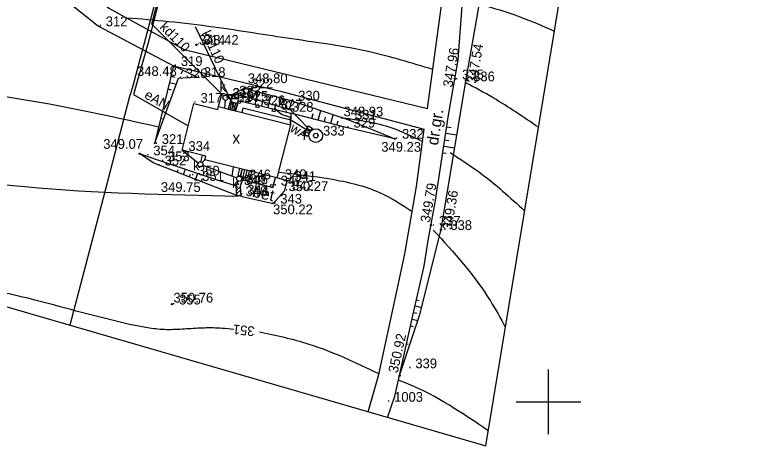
# Model space of a CAD drawing. Extents: x 4632591 to 4653165, y 5351032 to 5369868.
# Drawn here: x 4644617.6 to 4644733.1, y 5358293.2 to 5358359.7 of the extents above; entities that cross this region are included whole.
import ezdxf

# ---------------------------------------------------------------- set-up
doc = ezdxf.new("R2010")
doc.units = 0
for name, color, linetype in [('EBTPO_346', 7, 'Continuous'), ('EBTPO_352', 7, 'Continuous'), ('EBUPO_314', 7, 'Continuous'), ('EBUPP_312', 7, 'Continuous'), ('EBUPP_316', 7, 'Continuous'), ('EUZPU_424', 7, 'Continuous'), ('SDRPK_423', 7, 'Continuous'), ('UEEPO_585', 7, 'Continuous'), ('UKKPA_506', 7, 'Continuous'), ('UKKPA_509', 7, 'Continuous'), ('UKKPB_562', 7, 'Continuous'), ('UWWPA_907', 7, 'Continuous'), ('UWWPO_581', 7, 'Continuous'), ('Warstwa 40', 7, 'Continuous'), ('Warstwa 60', 7, 'Continuous'), ('Warstwa 62', 7, 'Continuous'), ('WUKPS_403', 7, 'Continuous'), ('WUKPS_820', 7, 'Continuous'), ('WUKPS_823', 7, 'Continuous'), ('WUKPS_824', 7, 'Continuous'), ('WWRPH_811', 7, 'Continuous')]:
    doc.layers.add(name, color=color, linetype=linetype)

msp = doc.modelspace()

# ---------------------------------------------------------------- linework, layer by layer
at = {"layer": 'EBTPO_346'}
for points in [[(4644652.02, 5358346.12), (4644652.11, 5358346.5), (4644652.51, 5358346.4), (4644652.42, 5358346.02)], [(4644654.81, 5358345.46), (4644654.91, 5358345.84), (4644655.31, 5358345.74), (4644655.21, 5358345.36)], [(4644657.33, 5358344.85), (4644657.43, 5358345.23), (4644657.83, 5358345.13), (4644657.73, 5358344.75)], [(4644652.78, 5358334.26), (4644652.88, 5358334.64), (4644653.28, 5358334.54), (4644653.19, 5358334.16)], [(4644657.05, 5358333.18), (4644657.14, 5358333.56), (4644657.54, 5358333.46), (4644657.45, 5358333.08)]]:
    msp.add_lwpolyline(points, close=True, dxfattribs=at)
at = {"layer": 'EBTPO_352'}
for p, q in [((4644650.85, 5358346.31), (4644650.56, 5358345.18)), ((4644650.84, 5358345.11), (4644651.12, 5358346.24)), ((4644651.13, 5358345.03), (4644651.42, 5358346.16)), ((4644651.42, 5358344.96), (4644651.71, 5358346.09)), ((4644651.99, 5358346.02), (4644651.7, 5358344.89)), ((4644652.71, 5358335.89), (4644652.45, 5358334.86)), ((4644652.45, 5358334.86), (4644652.71, 5358335.89)), ((4644653.09, 5358335.8), (4644652.82, 5358334.76)), ((4644653.45, 5358335.7), (4644653.18, 5358334.67)), ((4644653.8, 5358335.61), (4644653.54, 5358334.58))]:
    msp.add_line(p, q, dxfattribs=at)
for points in [[(4644651.99, 5358346.02), (4644650.85, 5358346.31), (4644650.56, 5358345.18), (4644651.7, 5358344.89)], [(4644652.32, 5358335.99), (4644652.06, 5358334.95), (4644653.93, 5358334.48), (4644654.19, 5358335.52)]]:
    msp.add_lwpolyline(points, close=True, dxfattribs=at)
at = {"layer": 'EBUPO_314'}
msp.add_line((4644652.02, 5358346.12), (4644651.7, 5358344.89), dxfattribs=at)
for points in [[(4644652.51, 5358346.4), (4644654.91, 5358345.84), (4644655.31, 5358345.74), (4644657.43, 5358345.23), (4644657.83, 5358345.13), (4644660.21, 5358344.54), (4644660.15, 5358342.76)], [(4644652.9, 5358334.74), (4644652.78, 5358334.26), (4644653.19, 5358334.16), (4644657.45, 5358333.08), (4644657.83, 5358334.6)]]:
    msp.add_lwpolyline(points, dxfattribs=at)
at = {"layer": 'EBUPP_312'}
msp.add_lwpolyline([(4644649.07, 5358345.55), (4644660.15, 5358342.76), (4644658.07, 5358334.54), (4644646.96, 5358337.34), (4644647.1, 5358337.91), (4644643.44, 5358338.83), (4644645.25, 5358346.01), (4644648.95, 5358345.08), (4644649.07, 5358345.55)], dxfattribs=at)
at = {"layer": 'EBUPP_316'}
for p, q in [((4644651.85, 5358332.63), (4644652.41, 5358333.11)), ((4644651.89, 5358332.16), (4644652.44, 5358332.64))]:
    msp.add_line(p, q, dxfattribs=at)
for points in [[(4644652.9, 5358334.74), (4644652.78, 5358334.26), (4644652.4, 5358333.29), (4644652.49, 5358331.73), (4644651.91, 5358331.82), (4644651.8, 5358333.32), (4644652.07, 5358334.06)], [(4644652.33, 5358334.81), (4644652.35, 5358334.88)]]:
    msp.add_lwpolyline(points, dxfattribs=at)
at = {"layer": 'EUZPU_424'}
for points in [[(4644607.61, 5358432.17), (4644607.56, 5358392.86), (4644609.22, 5358382.47), (4644616.62, 5358369.06), (4644630.54, 5358357.95), (4644642.13, 5358351.82), (4644658.62, 5358347.91), (4644680.81, 5358342.06)], [(4644675.12, 5358297.6), (4644676.25, 5358300.88), (4644677, 5358304.09), (4644679.07, 5358313.34), (4644680.72, 5358320.71), (4644680.92, 5358321.59), (4644681.43, 5358324.88), (4644682.54, 5358331.06), (4644684.5, 5358343.9), (4644686.02, 5358352.78), (4644686.73, 5358361.76), (4644688.28, 5358374.66), (4644687.59, 5358381.7), (4644684.88, 5358385.07), (4644678.84, 5358389.1), (4644673.9, 5358392.63), (4644663.63, 5358399.66), (4644641.5, 5358414), (4644622.58, 5358426.64)], [(4644610.34, 5358417.96), (4644610.89, 5358393.08), (4644612.64, 5358383.16), (4644619.15, 5358371.52), (4644632.13, 5358360.72), (4644643.74, 5358354.36), (4644681.29, 5358345.24)], [(4644681.29, 5358345.24), (4644683.66, 5358362.73), (4644686.26, 5358374.61), (4644685.41, 5358380.35), (4644682.83, 5358382.95)], [(4644672.14, 5358298.47), (4644673.79, 5358304.21), (4644676.97, 5358318.98), (4644677.79, 5358322.83), (4644679.59, 5358333.23), (4644680.81, 5358342.06)]]:
    msp.add_lwpolyline(points, dxfattribs=at)
at = {"layer": 'SDRPK_423'}
for points in [[(4644649.07, 5358345.55), (4644649.63, 5358347.64), (4644651.11, 5358347.25), (4644650.85, 5358346.31)], [(4644660.15, 5358342.76), (4644660.19, 5358343.87), (4644658.78, 5358344.34), (4644657.83, 5358345.13)], [(4644652.49, 5358331.73), (4644657.48, 5358330.59), (4644659.27, 5358332.63), (4644659.65, 5358334.08), (4644658.07, 5358334.54)]]:
    msp.add_lwpolyline(points, dxfattribs=at)
at = {"layer": 'UEEPO_585'}
msp.add_lwpolyline([(4644650.14, 5358401.9), (4644648.58, 5358395.61), (4644643.1, 5358374.42), (4644638.14, 5358355.24), (4644635.92, 5358347.4), (4644644.38, 5358342.57)], dxfattribs=at)
at = {"layer": 'UKKPA_506'}
for centre in [(4644650.13, 5358346.91), (4644646.25, 5358336.65), (4644652.24, 5358334.42)]:
    msp.add_circle(centre, 0.4, dxfattribs=at)
at = {"layer": 'UKKPA_509'}
for p, q in [((4644651.14, 5358347.44), (4644651.14, 5358346.74)), ((4644651.64, 5358346.74), (4644651.64, 5358347.44)), ((4644662.43, 5358341.73), (4644663.04, 5358341.38)), ((4644663.28, 5358341.82), (4644662.68, 5358342.16))]:
    msp.add_line(p, q, dxfattribs=at)
for points in [[(4644650.64, 5358347.44), (4644652.14, 5358347.44), (4644652.14, 5358346.74), (4644650.64, 5358346.74)], [(4644662.18, 5358341.3), (4644662.92, 5358342.6), (4644663.53, 5358342.25), (4644662.79, 5358340.95)]]:
    msp.add_lwpolyline(points, close=True, dxfattribs=at)
at = {"layer": 'UKKPB_562'}
for p, q in [((4644651.74, 5358344.88), (4644645.52, 5358357.88)), ((4644650.04, 5358345.31), (4644650.11, 5358346.51)), ((4644650.64, 5358347.02), (4644650.52, 5358346.99)), ((4644643.44, 5358338.83), (4644645.93, 5358336.89)), ((4644646.35, 5358337.03), (4644646.6, 5358338.04)), ((4644646.96, 5358337.34), (4644646.53, 5358336.93)), ((4644646.62, 5358336.51), (4644651.86, 5358334.56)), ((4644651.14, 5358334.83), (4644651.38, 5358336.23))]:
    msp.add_line(p, q, dxfattribs=at)
for points in [[(4644649.85, 5358347.19), (4644638.77, 5358358.29), (4644649.18, 5358398.88), (4644649.28, 5358402.17), (4644649.38, 5358405.5), (4644649.52, 5358410.28)], [(4644650.93, 5358405.16), (4644650.51, 5358404.58), (4644649.04, 5358399.14), (4644647.17, 5358392.02), (4644638.89, 5358360.17), (4644635.8, 5358348.55), (4644635.32, 5358347.09), (4644631.25, 5358331.42), (4644626.09, 5358311.85)], [(4644662.77, 5358342.32), (4644660.2, 5358344.99), (4644652.66, 5358347.28), (4644652.14, 5358347.22)]]:
    msp.add_lwpolyline(points, dxfattribs=at)
at = {"layer": 'UWWPA_907'}
for radius in [1.05, 0.35]:
    msp.add_circle((4644664.07, 5358341.08), radius, dxfattribs=at)
at = {"layer": 'UWWPO_581'}
msp.add_lwpolyline([(4644663.18, 5358341.63), (4644660.21, 5358343.48), (4644652.81, 5358345.3), (4644652.65, 5358344.65)], dxfattribs=at)
at = {"layer": 'Warstwa 40'}
msp.add_lwpolyline([(4644810.83, 5358555.03), (4644734.32, 5358627.59), (4644688.9, 5358576.34), (4644696.21, 5358541.05), (4644665.65, 5358513.08), (4644675.21, 5358482.87), (4644634.26, 5358446.15), (4644624.66, 5358448.08), (4644610.34, 5358444.41), (4644593.08, 5358445.77), (4644584.82, 5358446.42), (4644558.95, 5358331.35), (4644690.29, 5358293.2), (4644705.73, 5358386.52), (4644692.29, 5358404.57), (4644776.59, 5358522.67)], close=True, dxfattribs=at)
at = {"layer": 'Warstwa 60'}
for p, q in [((4644700, 5358295), (4644700, 5358305)), ((4644695, 5358300), (4644705, 5358300))]:
    msp.add_line(p, q, dxfattribs=at)
at = {"layer": 'WUKPS_403'}
for centre in [(4644645.64, 5358355.09), (4644642.13, 5358351.82), (4644685.53, 5358349.85), (4644687.26, 5358349.6), (4644687.26, 5358349.6), (4644653.07, 5358348.42), (4644668.15, 5358343.82), (4644676.26, 5358340.6), (4644636.87, 5358338.29), (4644645.5, 5358334.28), (4644659.65, 5358334.08), (4644657.48, 5358330.64), (4644681.85, 5358327.27), (4644683.39, 5358326.56), (4644641.89, 5358315.09), (4644677.01, 5358304.05)]:
    msp.add_circle(centre, 0.09, dxfattribs=at)
at = {"layer": 'WUKPS_820'}
for p, q in [((4644642.2, 5358351.79), (4644642.17, 5358351.73)), ((4644643.54, 5358351.15), (4644643.25, 5358350.55)), ((4644641.74, 5358350.23), (4644642.32, 5358350.08)), ((4644641.51, 5358349.28), (4644642.56, 5358349.02)), ((4644641.26, 5358348.27), (4644641.73, 5358348.15)), ((4644654.69, 5358345.89), (4644655.14, 5358347.83)), ((4644656.72, 5358345.4), (4644657.18, 5358347.29)), ((4644653.67, 5358346.13), (4644653.9, 5358347.11)), ((4644655.73, 5358345.64), (4644655.96, 5358346.6)), ((4644657.69, 5358345.16), (4644657.93, 5358346.1)), ((4644640.64, 5358345.73), (4644640.97, 5358345.65)), ((4644664.46, 5358343.44), (4644664.85, 5358344.94)), ((4644640.16, 5358343.78), (4644640.38, 5358343.72)), ((4644640.41, 5358344.79), (4644640.96, 5358344.65)), ((4644663.45, 5358343.7), (4644663.66, 5358344.49)), ((4644665.4, 5358343.2), (4644665.58, 5358343.92)), ((4644666.4, 5358342.94), (4644666.76, 5358344.3)), ((4644667.34, 5358342.69), (4644667.51, 5358343.34)), ((4644684.13, 5358341.46), (4644685.85, 5358341.2)), ((4644684.28, 5358342.42), (4644684.96, 5358342.32)), ((4644683.97, 5358340.43), (4644684.58, 5358340.33)), ((4644683.83, 5358339.47), (4644685.52, 5358339.21)), ((4644683.67, 5358338.44), (4644684.21, 5358338.35)), ((4644642.66, 5358335.44), (4644642.81, 5358335.84)), ((4644643.63, 5358335.06), (4644643.96, 5358335.89)), ((4644644.54, 5358334.71), (4644644.71, 5358335.15)), ((4644645.51, 5358334.33), (4644645.87, 5358335.25)), ((4644646.41, 5358333.97), (4644646.6, 5358334.45)), ((4644679.61, 5358315.75), (4644680.03, 5358315.66)), ((4644679.17, 5358313.78), (4644679.65, 5358313.67)), ((4644679.4, 5358314.8), (4644680.39, 5358314.58)), ((4644678.94, 5358312.76), (4644679.81, 5358312.56)), ((4644678.72, 5358311.74), (4644679.1, 5358311.65)), ((4644678.1, 5358308.97), (4644678.34, 5358308.92)), ((4644677.49, 5358306.28), (4644677.71, 5358306.23))]:
    msp.add_line(p, q, dxfattribs=at)
at = {"layer": 'WUKPS_823'}
for points in [[(4644645.68, 5358350.12), (4644642.13, 5358351.82), (4644639.18, 5358339.79)], [(4644676.26, 5358340.6), (4644668.78, 5358342.32), (4644660.21, 5358344.54)], [(4644651.91, 5358331.82), (4644638.97, 5358336.89), (4644636.86, 5358338.33)]]:
    msp.add_lwpolyline(points, dxfattribs=at)
at = {"layer": 'WUKPS_824'}
for points in [[(4644677, 5358304.09), (4644680.12, 5358313.49), (4644683.4, 5358326.62), (4644687.24, 5358349.46), (4644689.07, 5358360.02), (4644691.79, 5358376.83), (4644689.46, 5358383.55), (4644685.66, 5358386.59), (4644679.89, 5358391.82), (4644676.65, 5358399.24), (4644671.43, 5358401.93), (4644666.89, 5358400.78)], [(4644639.18, 5358339.79), (4644642.9, 5358349.94), (4644645.68, 5358350.12)], [(4644651.17, 5358347.44), (4644653.03, 5358348.38), (4644660.24, 5358346.49), (4644669.01, 5358343.55), (4644676.26, 5358340.6)], [(4644636.86, 5358338.33), (4644639.48, 5358337.41), (4644649.14, 5358334.15), (4644651.8, 5358333.32)]]:
    msp.add_lwpolyline(points, dxfattribs=at)
at = {"layer": 'WWRPH_811'}
for points in [[(4644689.29, 5358361.38), (4644695.57, 5358359.42), (4644700.88, 5358357.19)], [(4644682.11, 5358351.28), (4644672.36, 5358353.99), (4644660.38, 5358356), (4644648.36, 5358357.8), (4644641.32, 5358358.65), (4644634.89, 5358359.21)], [(4644590.97, 5358352.67), (4644594.78, 5358351.43), (4644596.7, 5358350.86), (4644598.64, 5358350.34), (4644604.16, 5358349.11), (4644609.7, 5358348.09), (4644615.28, 5358347.26), (4644639.83, 5358342.45)], [(4644698.42, 5358342.36), (4644691.45, 5358346.89), (4644687.19, 5358349.24)], [(4644668.18, 5358343.83), (4644675.79, 5358342.29), (4644680.55, 5358340.18)], [(4644684.8, 5358338.46), (4644689.37, 5358335.38), (4644696.29, 5358329.48)], [(4644588.68, 5358337.51), (4644619.23, 5358333.21), (4644652.1, 5358331.74)], [(4644658.3, 5358335.43), (4644666.35, 5358334.39), (4644673.9, 5358332.3), (4644678.93, 5358329.39)], [(4644682.21, 5358326.51), (4644691.01, 5358315.6), (4644693.32, 5358311.52)], [(4644651.42, 5358311.17), (4644649.6, 5358311.34), (4644646.87, 5358311.4), (4644644.13, 5358311.25), (4644641.4, 5358311.14), (4644640.04, 5358311.18), (4644638.69, 5358311.34), (4644632.03, 5358312.74), (4644625.43, 5358314.46), (4644618.83, 5358316.18), (4644615.51, 5358316.92), (4644612.17, 5358317.54), (4644600.28, 5358319.44)], [(4644673.82, 5358304.33), (4644663.03, 5358308.88), (4644655.36, 5358310.77)], [(4644690.68, 5358295.55), (4644678.38, 5358302.74), (4644676.83, 5358303.35)]]:
    msp.add_spline(points, degree=3, dxfattribs=at)

# ---------------------------------------------------------------- texts
at = {"layer": 'EBUPP_312'}
msp.add_text('x', height=1.8, dxfattribs=at).set_placement((4644651.19, 5358339.82))
at = {"layer": 'EUZPU_424'}
msp.add_text('dr.gr.', height=1.8, rotation=81.2897, dxfattribs=at).set_placement((4644682.92, 5358339.5))
at = {"layer": 'SDRPK_423'}
msp.add_text('bet', height=1.8, rotation=347.1127, dxfattribs=at).set_placement((4644654.18, 5358331.67))
at = {"layer": 'UEEPO_585'}
msp.add_text('eAN', height=1.5, rotation=330.2557, dxfattribs=at).set_placement((4644637.49, 5358346.94))
at = {"layer": 'UKKPA_506'}
for p in [(4644649.21, 5358347.85), (4644645.12, 5358335.7), (4644651.15, 5358333)]:
    msp.add_text('k', height=1.5, dxfattribs=at).set_placement(p)
at = {"layer": 'UKKPB_562'}
for s, rotation, p in [('kd110', 314.9546, (4644639.89, 5358357.7)), ('ks110', 295.5747, (4644646.4, 5358356.85)), ('kd', 343.1311, (4644658.16, 5358345.65))]:
    msp.add_text(s, height=1.5, rotation=rotation, dxfattribs=at).set_placement(p)
at = {"layer": 'UWWPO_581'}
msp.add_text('wA', height=1.5, rotation=328.1595, dxfattribs=at).set_placement((4644659.96, 5358341.82))
at = {"layer": 'Warstwa 62'}
for s, p in [('. 312', (4644630.54, 5358357.95)), ('. 314', (4644645.64, 5358355.09)), ('. 319', (4644642.13, 5358351.82)), ('. 320', (4644642.9, 5358349.94)), ('. 318', (4644645.68, 5358350.12)), ('. 335', (4644685.54, 5358349.75)), ('. 336', (4644687.24, 5358349.46)), ('. 322', (4644653.03, 5358348.38)), ('. 316', (4644650.09, 5358346.87)), ('. 315', (4644650.13, 5358346.91)), ('. 323', (4644651.12, 5358347.25)), ('. 317', (4644645.16, 5358346.14)), ('. 324', (4644650.81, 5358346.26)), ('. 325', (4644652.26, 5358346.44)), ('. 326', (4644654.89, 5358345.76)), ('. 330', (4644660.24, 5358346.49)), ('. 327', (4644657.55, 5358345.1)), ('. 328', (4644659.26, 5358344.76)), ('. 331', (4644669.01, 5358343.55)), ('. 329', (4644668.78, 5358342.32)), ('. 333', (4644664.07, 5358341.08)), ('. 332', (4644676.26, 5358340.6)), ('. 321', (4644639.18, 5358339.79)), ('. 354', (4644637.88, 5358338.03)), ('. 334', (4644643.3, 5358338.71)), ('. 352', (4644639.62, 5358336.47)), ('. 353', (4644640.15, 5358337.13)), ('. 350', (4644644.78, 5358334.94)), ('. 346', (4644652.68, 5358334.33)), ('. 340', (4644658.18, 5358334.38)), ('. 351', (4644645.42, 5358334.08)), ('. 349', (4644651.85, 5358333.47)), ('. 345', (4644652.24, 5358333.57)), ('. 347', (4644657.54, 5358333.38)), ('. 341', (4644659.65, 5358334.08)), ('. 344', (4644652.38, 5358331.98)), ('. 342', (4644659.27, 5358332.63)), ('. 348', (4644652.1, 5358331.74)), ('. 343', (4644657.48, 5358330.59)), ('. 337', (4644681.96, 5358327.18)), ('. 338', (4644683.72, 5358326.52)), ('. 355', (4644641.86, 5358315.03)), ('. 339', (4644678.32, 5358305.19)), ('. 1003', (4644675.04, 5358300.02)), ('. 1003', (4644675.04, 5358300.02)), ('. 1003', (4644675.04, 5358300.02)), ('. 1003', (4644675.04, 5358300.02))]:
    msp.add_text(s, height=1.5, dxfattribs=at).set_placement(p)
at = {"layer": 'WUKPS_403'}
for s, p in [('348.42', (4644646.02, 5358355.09)), ('348.48', (4644636.48, 5358350.27)), ('348.80', (4644653.58, 5358349.17)), ('348.93', (4644668.35, 5358344.04)), ('349.07', (4644631.27, 5358339.04)), ('349.23', (4644674.18, 5358338.59)), ('349.75', (4644640.16, 5358332.39)), ('350.27', (4644659.86, 5358332.52)), ('350.22', (4644657.48, 5358328.95)), ('350.76', (4644642.1, 5358315.33))]:
    msp.add_text(s, height=1.5, dxfattribs=at).set_placement(p)
for s, rotation, p in [('347.96', 80.1685, (4644685.15, 5358348.45)), ('347.54', 80.1685, (4644688.87, 5358349.06)), ('349.79', 79.8243, (4644681.66, 5358327.58)), ('349.36', 80.4547, (4644685.04, 5358326.46)), ('350.92', 77.3935, (4644676.69, 5358304.37))]:
    msp.add_text(s, height=1.5, rotation=rotation, dxfattribs=at).set_placement(p)
at = {"layer": 'WWRPH_811'}
msp.add_text('351', height=1.5, rotation=174.22, dxfattribs=at).set_placement((4644654.69, 5358311.61))

doc.saveas('drawing.dxf')
